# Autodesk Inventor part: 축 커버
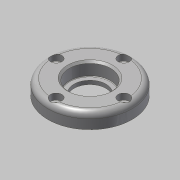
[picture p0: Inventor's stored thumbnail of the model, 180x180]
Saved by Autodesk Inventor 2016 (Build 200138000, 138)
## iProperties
Created: 2015-10
Part Number: 축 커버
Document SubType Name: Modeling
Designer: mdu
Density: 7.86 g/cm^3
Material: 강철, 연강
Mass: 76.1259 g
Surface Area: 48.0703 cm^2
Volume: 9.68523 cm^3
Appearance: 강철
Author: mdu
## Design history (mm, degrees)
sketch "스케치1"
  geometry: C1 r 22.355 at (0, 0) reference; C2 r 14 at (0, 0) reference; C3 r 1.23 at (0, 18) reference; 1 further point
extrude "돌출1" new body sketch "스케치1" distance "d0" = 8; taper "d1" = 0 deg
sketch "스케치2"
  geometry: C1 r 14 at (0, 0) reference; 1 further point
extrude "돌출2" join sketch "스케치2" distance "d2" = 3; taper "d3" = 0 deg
hole "구멍1" diameter "d6" = 17; stored, may be unused: countersink angle "d10" = 90 deg, drill point angle "d12" = 118 deg; dims "d4" = 10, "d5" = 10, "d7" = 6, "d8" = 23, "d9" = 2, "d11" = 8
hole "구멍2" diameter "d15" = 22; stored, may be unused: countersink angle "d19" = 90 deg, drill point angle "d21" = 0 deg; dims "d13" = 10, "d14" = 10, "d16" = 6, "d17" = 25, "d18" = 2, "d20" = 7
fillet "모깎기1" dims "d22" = 3, "d23" = 0.3
chamfer "모따기1" distance "d24" = 1; stored, may be unused: second distance "d25" = 2, angle "d26" = 45 deg
sketch "스케치3"
  geometry: 2 further points
hole "구멍3" sketch "스케치3" at (0, 18) diameter "d27" = 3.4; stored, may be unused: countersink angle "d31" = 90 deg, drill point angle "d33" = 118 deg; dims "d28" = 6, "d29" = 6, "d30" = 3.3, "d32" = 7
node "솔리드1"
pattern_circular "원형 패턴1" dims angle "d35" = 360 deg
node "참조1"
node "참조2"
node "참조3"
